// Mitsubishi GX Works2 project: LED通讯案例   PLC: FX3U/FX3UC

PROGRAM MAIN
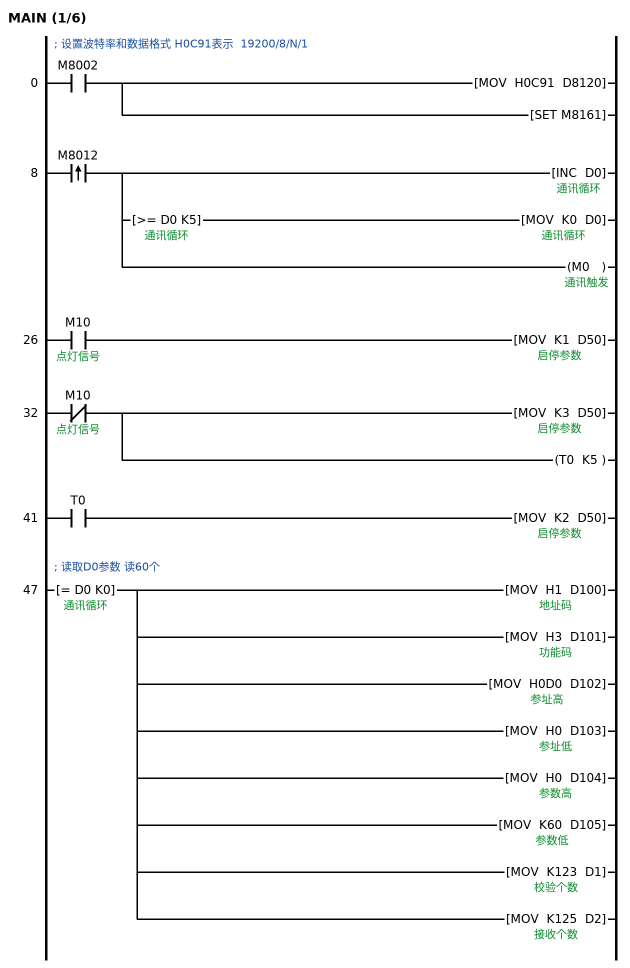
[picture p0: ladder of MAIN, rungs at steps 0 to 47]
; 设置波特率和数据格式 H0C91表示  19200/8/N/1
0     LD      M8002
      MOV     H0C91 D8120
      SET     M8161
8     LDP     M8012
      INC     D0  ; 通讯循环
      MPS
      AND>=   D0 K5  ; 通讯循环
      MOV     K0 D0
      MPP
      OUT     M0  ; 通讯触发
26    LD      M10  ; 点灯信号
      MOV     K1 D50  ; 启停参数
32    LDI     M10  ; 点灯信号
      MOV     K3 D50
      OUT     T0 K5
41    LD      T0
      MOV     K2 D50
; 读取D0参数 读60个
47    LD=     D0 K0  ; 通讯循环
      MOV     H1 D100  ; 地址码
      MOV     H3 D101  ; 功能码
      MOV     H0D0 D102  ; 参址高
      MOV     H0 D103  ; 参址低
      MOV     H0 D104  ; 参数高
      MOV     K60 D105  ; 参数低
      MOV     K123 D1  ; 校验个数
      MOV     K125 D2  ; 接收个数
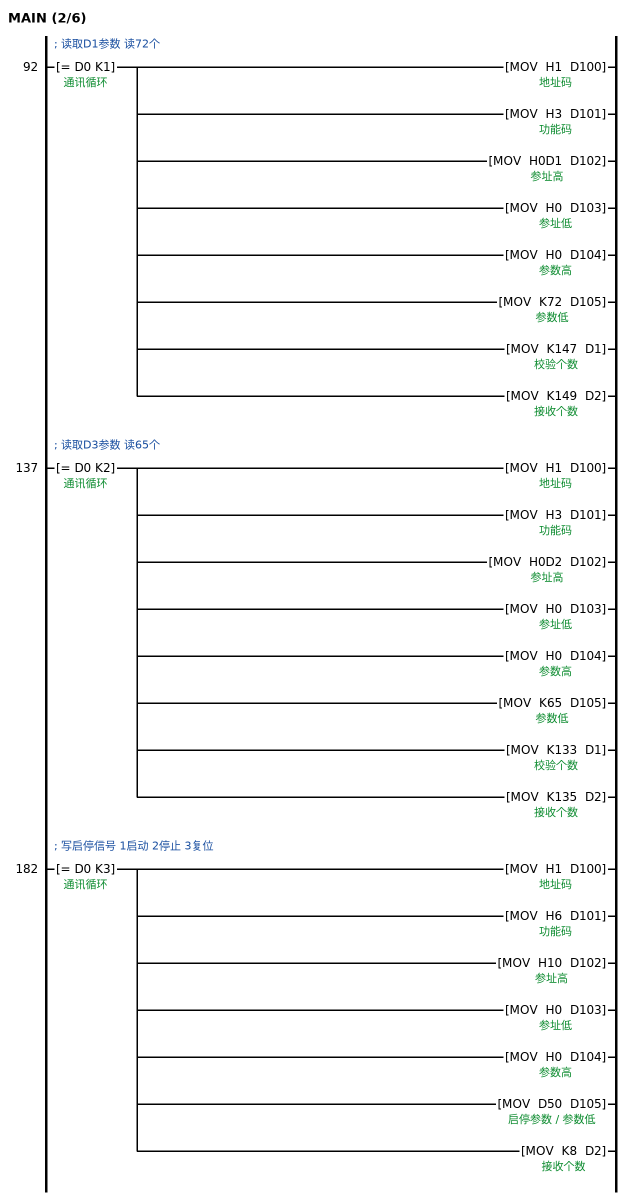
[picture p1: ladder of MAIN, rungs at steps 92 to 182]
; 读取D1参数 读72个
92    LD=     D0 K1  ; 通讯循环
      MOV     H1 D100
      MOV     H3 D101
      MOV     H0D1 D102
      MOV     H0 D103
      MOV     H0 D104
      MOV     K72 D105
      MOV     K147 D1
      MOV     K149 D2
; 读取D3参数 读65个
137   LD=     D0 K2  ; 通讯循环
      MOV     H1 D100
      MOV     H3 D101
      MOV     H0D2 D102
      MOV     H0 D103
      MOV     H0 D104
      MOV     K65 D105
      MOV     K133 D1
      MOV     K135 D2
; 写启停信号 1启动 2停止 3复位
182   LD=     D0 K3  ; 通讯循环
      MOV     H1 D100
      MOV     H6 D101
      MOV     H10 D102
      MOV     H0 D103
      MOV     H0 D104
      MOV     D50 D105
      MOV     K8 D2
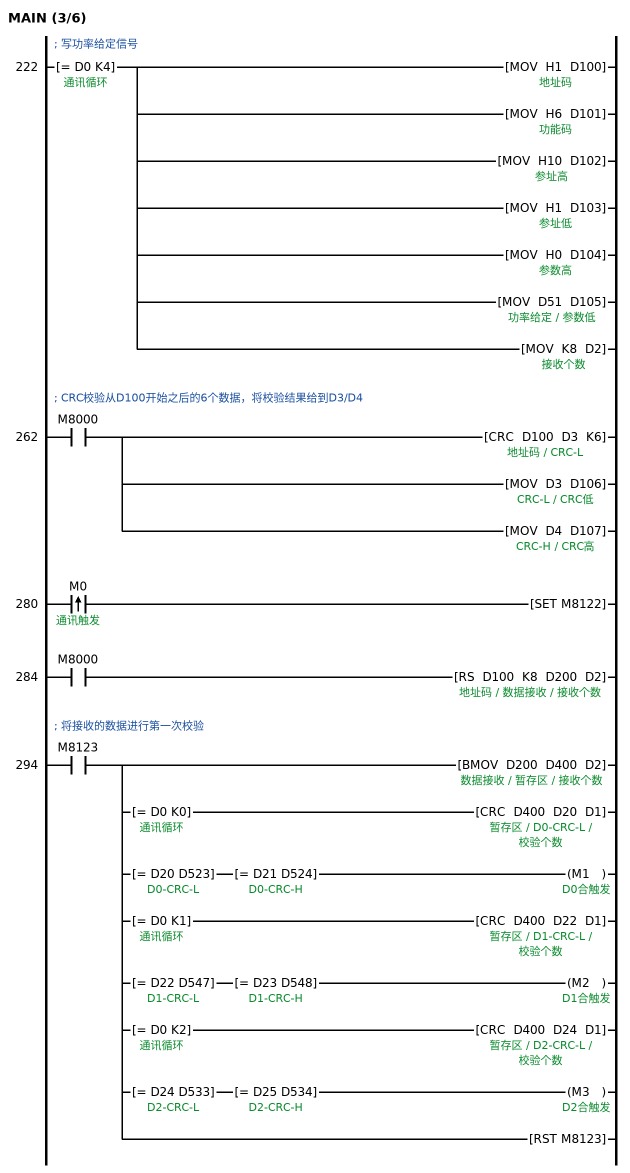
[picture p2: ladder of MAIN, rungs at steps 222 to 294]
; 写功率给定信号
222   LD=     D0 K4  ; 通讯循环
      MOV     H1 D100
      MOV     H6 D101
      MOV     H10 D102
      MOV     H1 D103
      MOV     H0 D104
      MOV     D51 D105  ; 功率给定
      MOV     K8 D2
; CRC校验从D100开始之后的6个数据，将校验结果给到D3/D4
262   LD      M8000
      CRC     D100 D3 K6  ; CRC-L
      MOV     D3 D106  ; CRC低
      MOV     D4 D107  ; CRC-H / CRC高
280   LDP     M0  ; 通讯触发
      SET     M8122
284   LD      M8000
      RS      D100 K8 D200 D2  ; 地址码 / 数据接收 / 接收个数
; 将接收的数据进行第一次校验
294   LD      M8123
      BMOV    D200 D400 D2  ; 暂存区
      MPS
      AND=    D0 K0  ; 通讯循环
      CRC     D400 D20 D1  ; D0-CRC-L
      MRD
      AND=    D20 D523  ; D0-CRC-L
      AND=    D21 D524  ; D0-CRC-H
      OUT     M1  ; D0合触发
      MRD
      AND=    D0 K1  ; 通讯循环
      CRC     D400 D22 D1  ; D1-CRC-L
      MRD
      AND=    D22 D547  ; D1-CRC-L
      AND=    D23 D548  ; D1-CRC-H
      OUT     M2  ; D1合触发
      MRD
      AND=    D0 K2  ; 通讯循环
      CRC     D400 D24 D1  ; D2-CRC-L
      MRD
      AND=    D24 D533  ; D2-CRC-L
      AND=    D25 D534  ; D2-CRC-H
      OUT     M3  ; D2合触发
      MPP
      RST     M8123
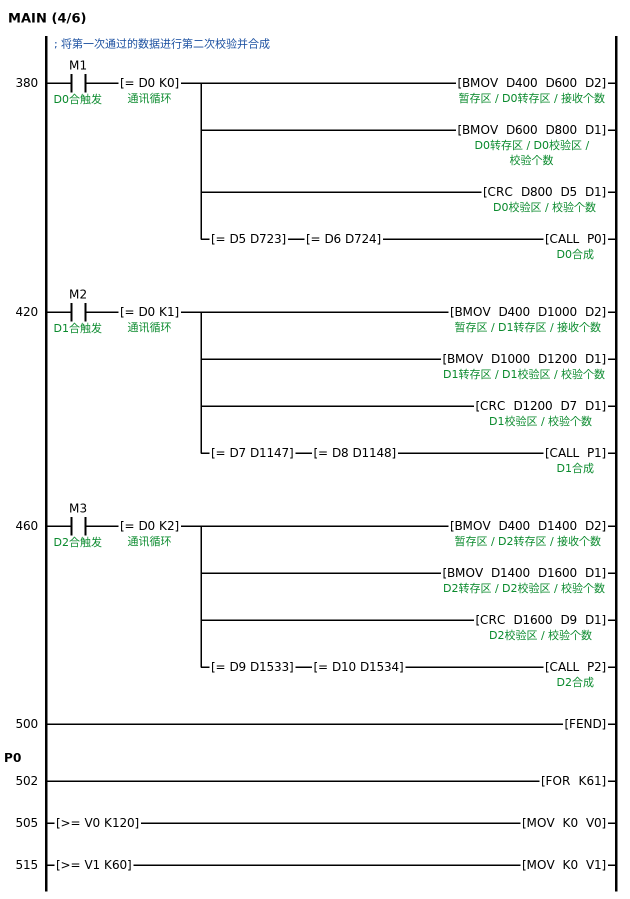
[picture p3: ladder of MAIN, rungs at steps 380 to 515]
; 将第一次通过的数据进行第二次校验并合成
380   LD      M1  ; D0合触发
      AND=    D0 K0  ; 通讯循环
      BMOV    D400 D600 D2  ; D0转存区
      BMOV    D600 D800 D1  ; D0校验区
      CRC     D800 D5 D1
      AND=    D5 D723
      AND=    D6 D724
      CALL    P0  ; D0合成
420   LD      M2  ; D1合触发
      AND=    D0 K1  ; 通讯循环
      BMOV    D400 D1000 D2  ; D1转存区
      BMOV    D1000 D1200 D1  ; D1校验区
      CRC     D1200 D7 D1
      AND=    D7 D1147
      AND=    D8 D1148
      CALL    P1  ; D1合成
460   LD      M3  ; D2合触发
      AND=    D0 K2  ; 通讯循环
      BMOV    D400 D1400 D2  ; D2转存区
      BMOV    D1400 D1600 D1  ; D2校验区
      CRC     D1600 D9 D1
      AND=    D9 D1533
      AND=    D10 D1534
      CALL    P2  ; D2合成
500   FEND
      P0
502   FOR     K61
505   LD>=    V0 K120
      MOV     K0 V0
515   LD>=    V1 K60
      MOV     K0 V1
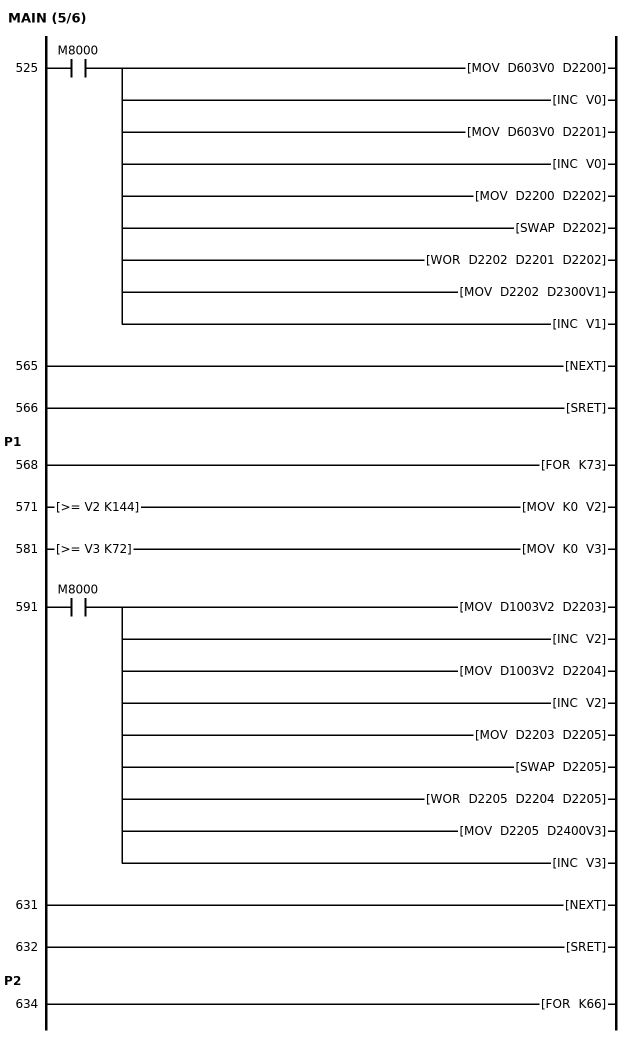
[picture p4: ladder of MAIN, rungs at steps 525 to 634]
525   LD      M8000
      MOV     D603V0 D2200
      INC     V0
      MOV     D603V0 D2201
      INC     V0
      MOV     D2200 D2202
      SWAP    D2202
      WOR     D2202 D2201 D2202
      MOV     D2202 D2300V1
      INC     V1
565   NEXT
566   SRET
      P1
568   FOR     K73
571   LD>=    V2 K144
      MOV     K0 V2
581   LD>=    V3 K72
      MOV     K0 V3
591   LD      M8000
      MOV     D1003V2 D2203
      INC     V2
      MOV     D1003V2 D2204
      INC     V2
      MOV     D2203 D2205
      SWAP    D2205
      WOR     D2205 D2204 D2205
      MOV     D2205 D2400V3
      INC     V3
631   NEXT
632   SRET
      P2
634   FOR     K66
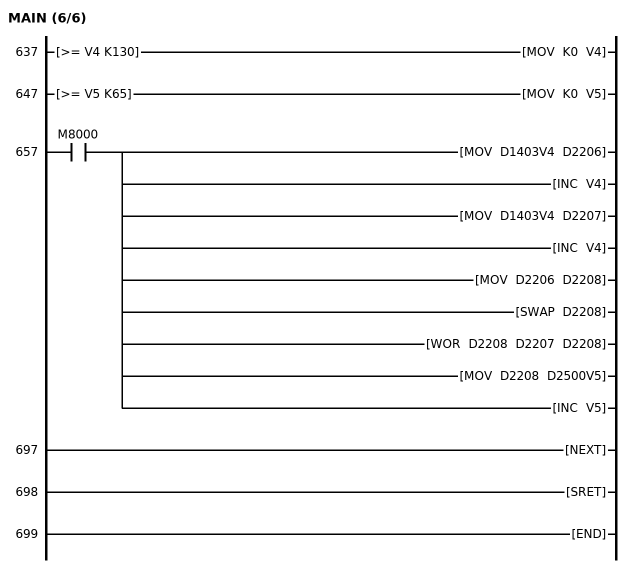
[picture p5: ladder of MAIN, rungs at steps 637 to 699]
637   LD>=    V4 K130
      MOV     K0 V4
647   LD>=    V5 K65
      MOV     K0 V5
657   LD      M8000
      MOV     D1403V4 D2206
      INC     V4
      MOV     D1403V4 D2207
      INC     V4
      MOV     D2206 D2208
      SWAP    D2208
      WOR     D2208 D2207 D2208
      MOV     D2208 D2500V5
      INC     V5
697   NEXT
698   SRET
699   END
END_PROGRAM

// device comments not shown above
D2300  ; D0结果
D2400  ; D1结果
D2500  ; D2结果
